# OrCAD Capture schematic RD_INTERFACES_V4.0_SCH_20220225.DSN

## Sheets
1 [1] REVISION HISTORY: title: REFERENCE DESIGN INTERFACE BOARD VERSION 3.2; rev: D
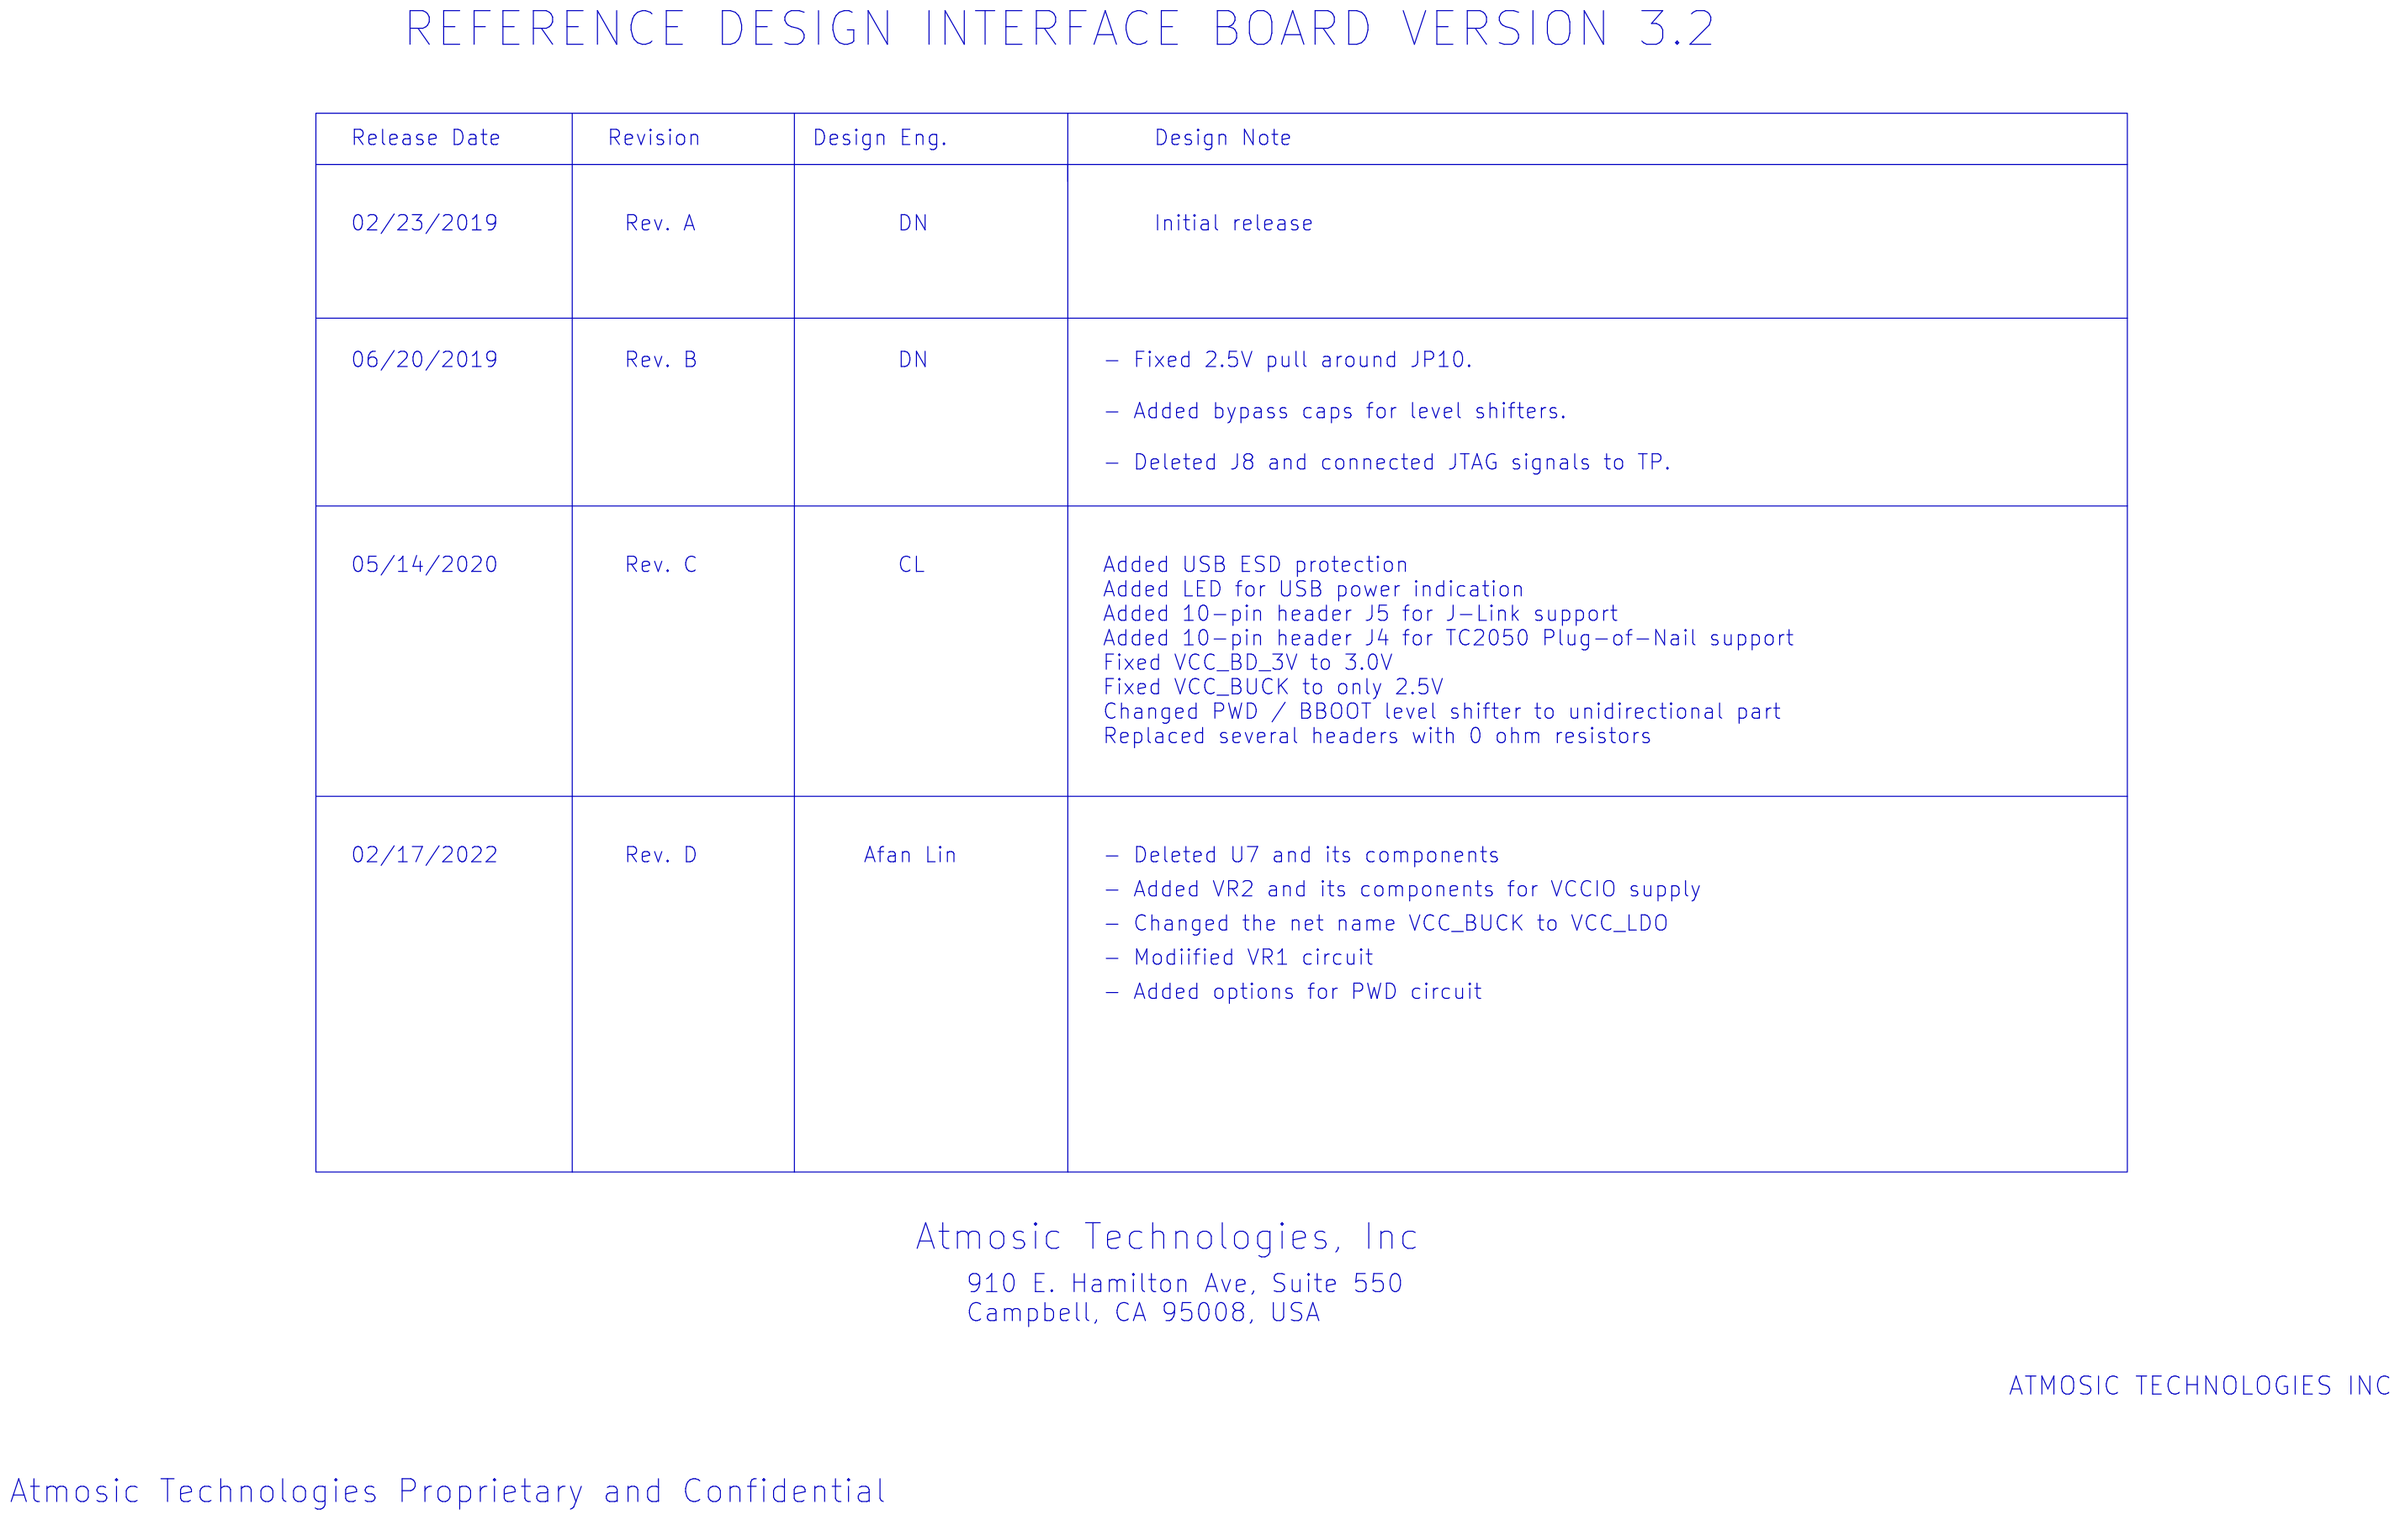
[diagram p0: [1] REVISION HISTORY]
2 [2] RD Connector: size B
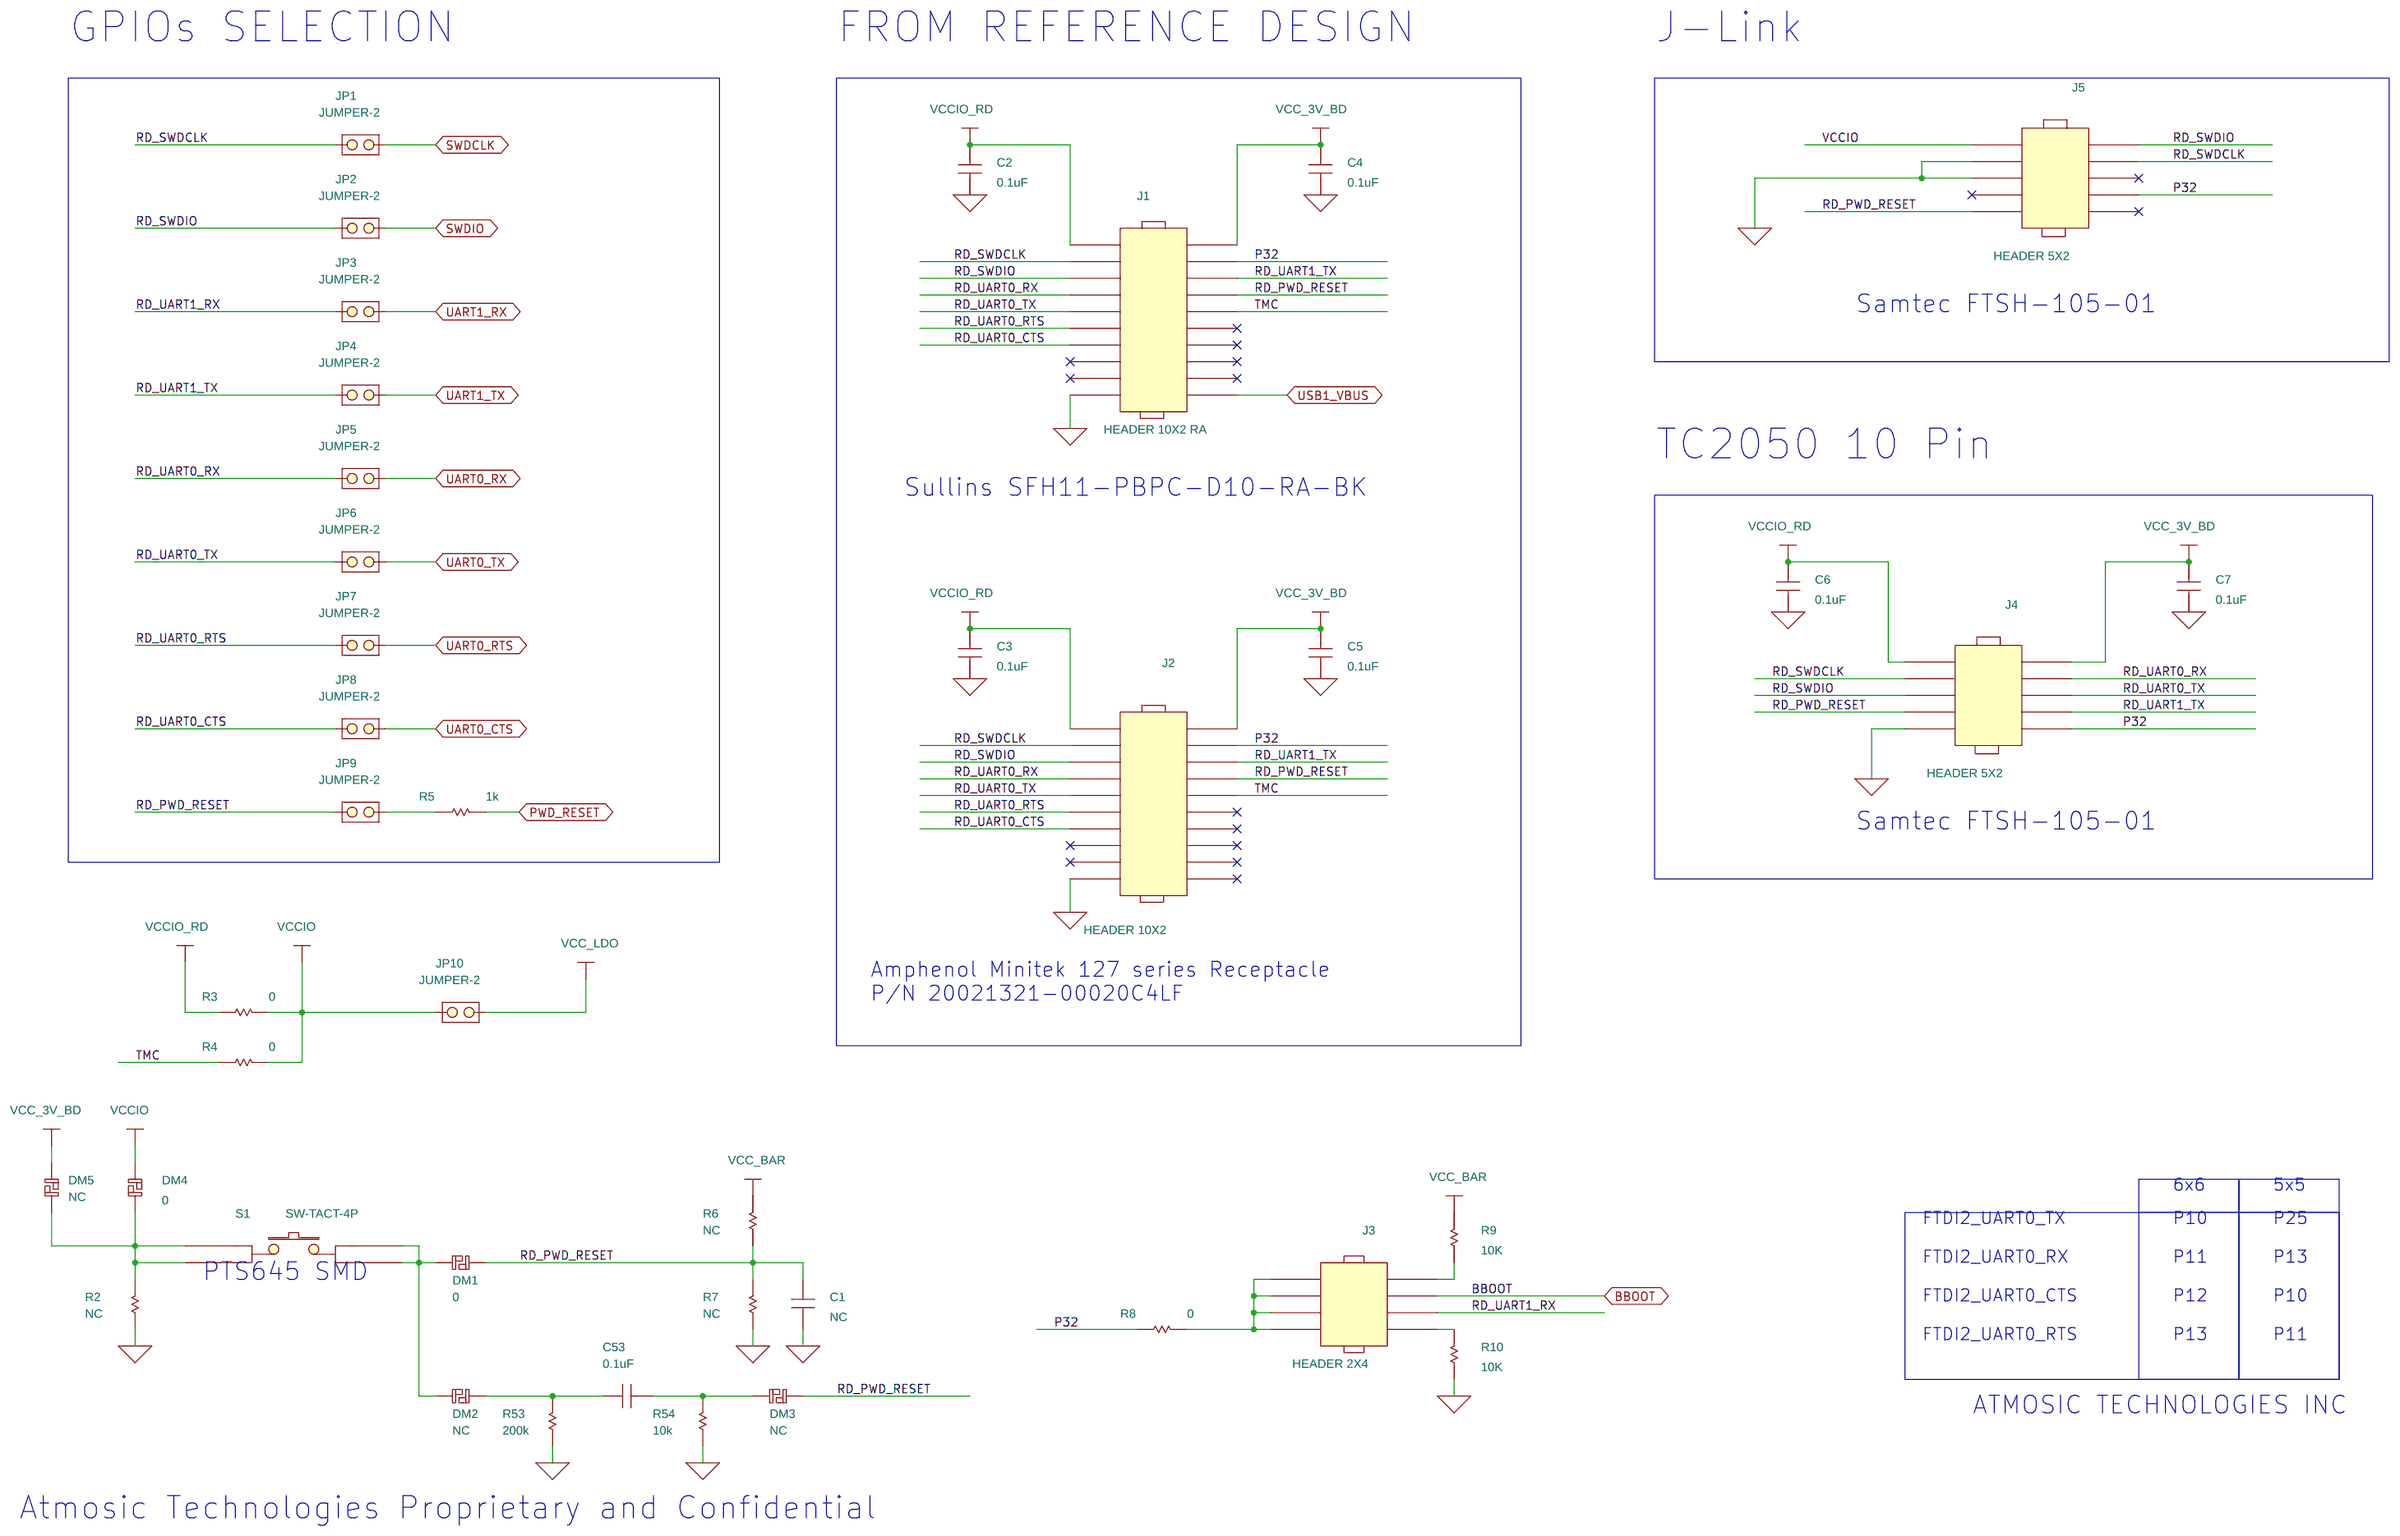
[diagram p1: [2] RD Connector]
3 [3] USB-Serial-MPSSE MODE: size B
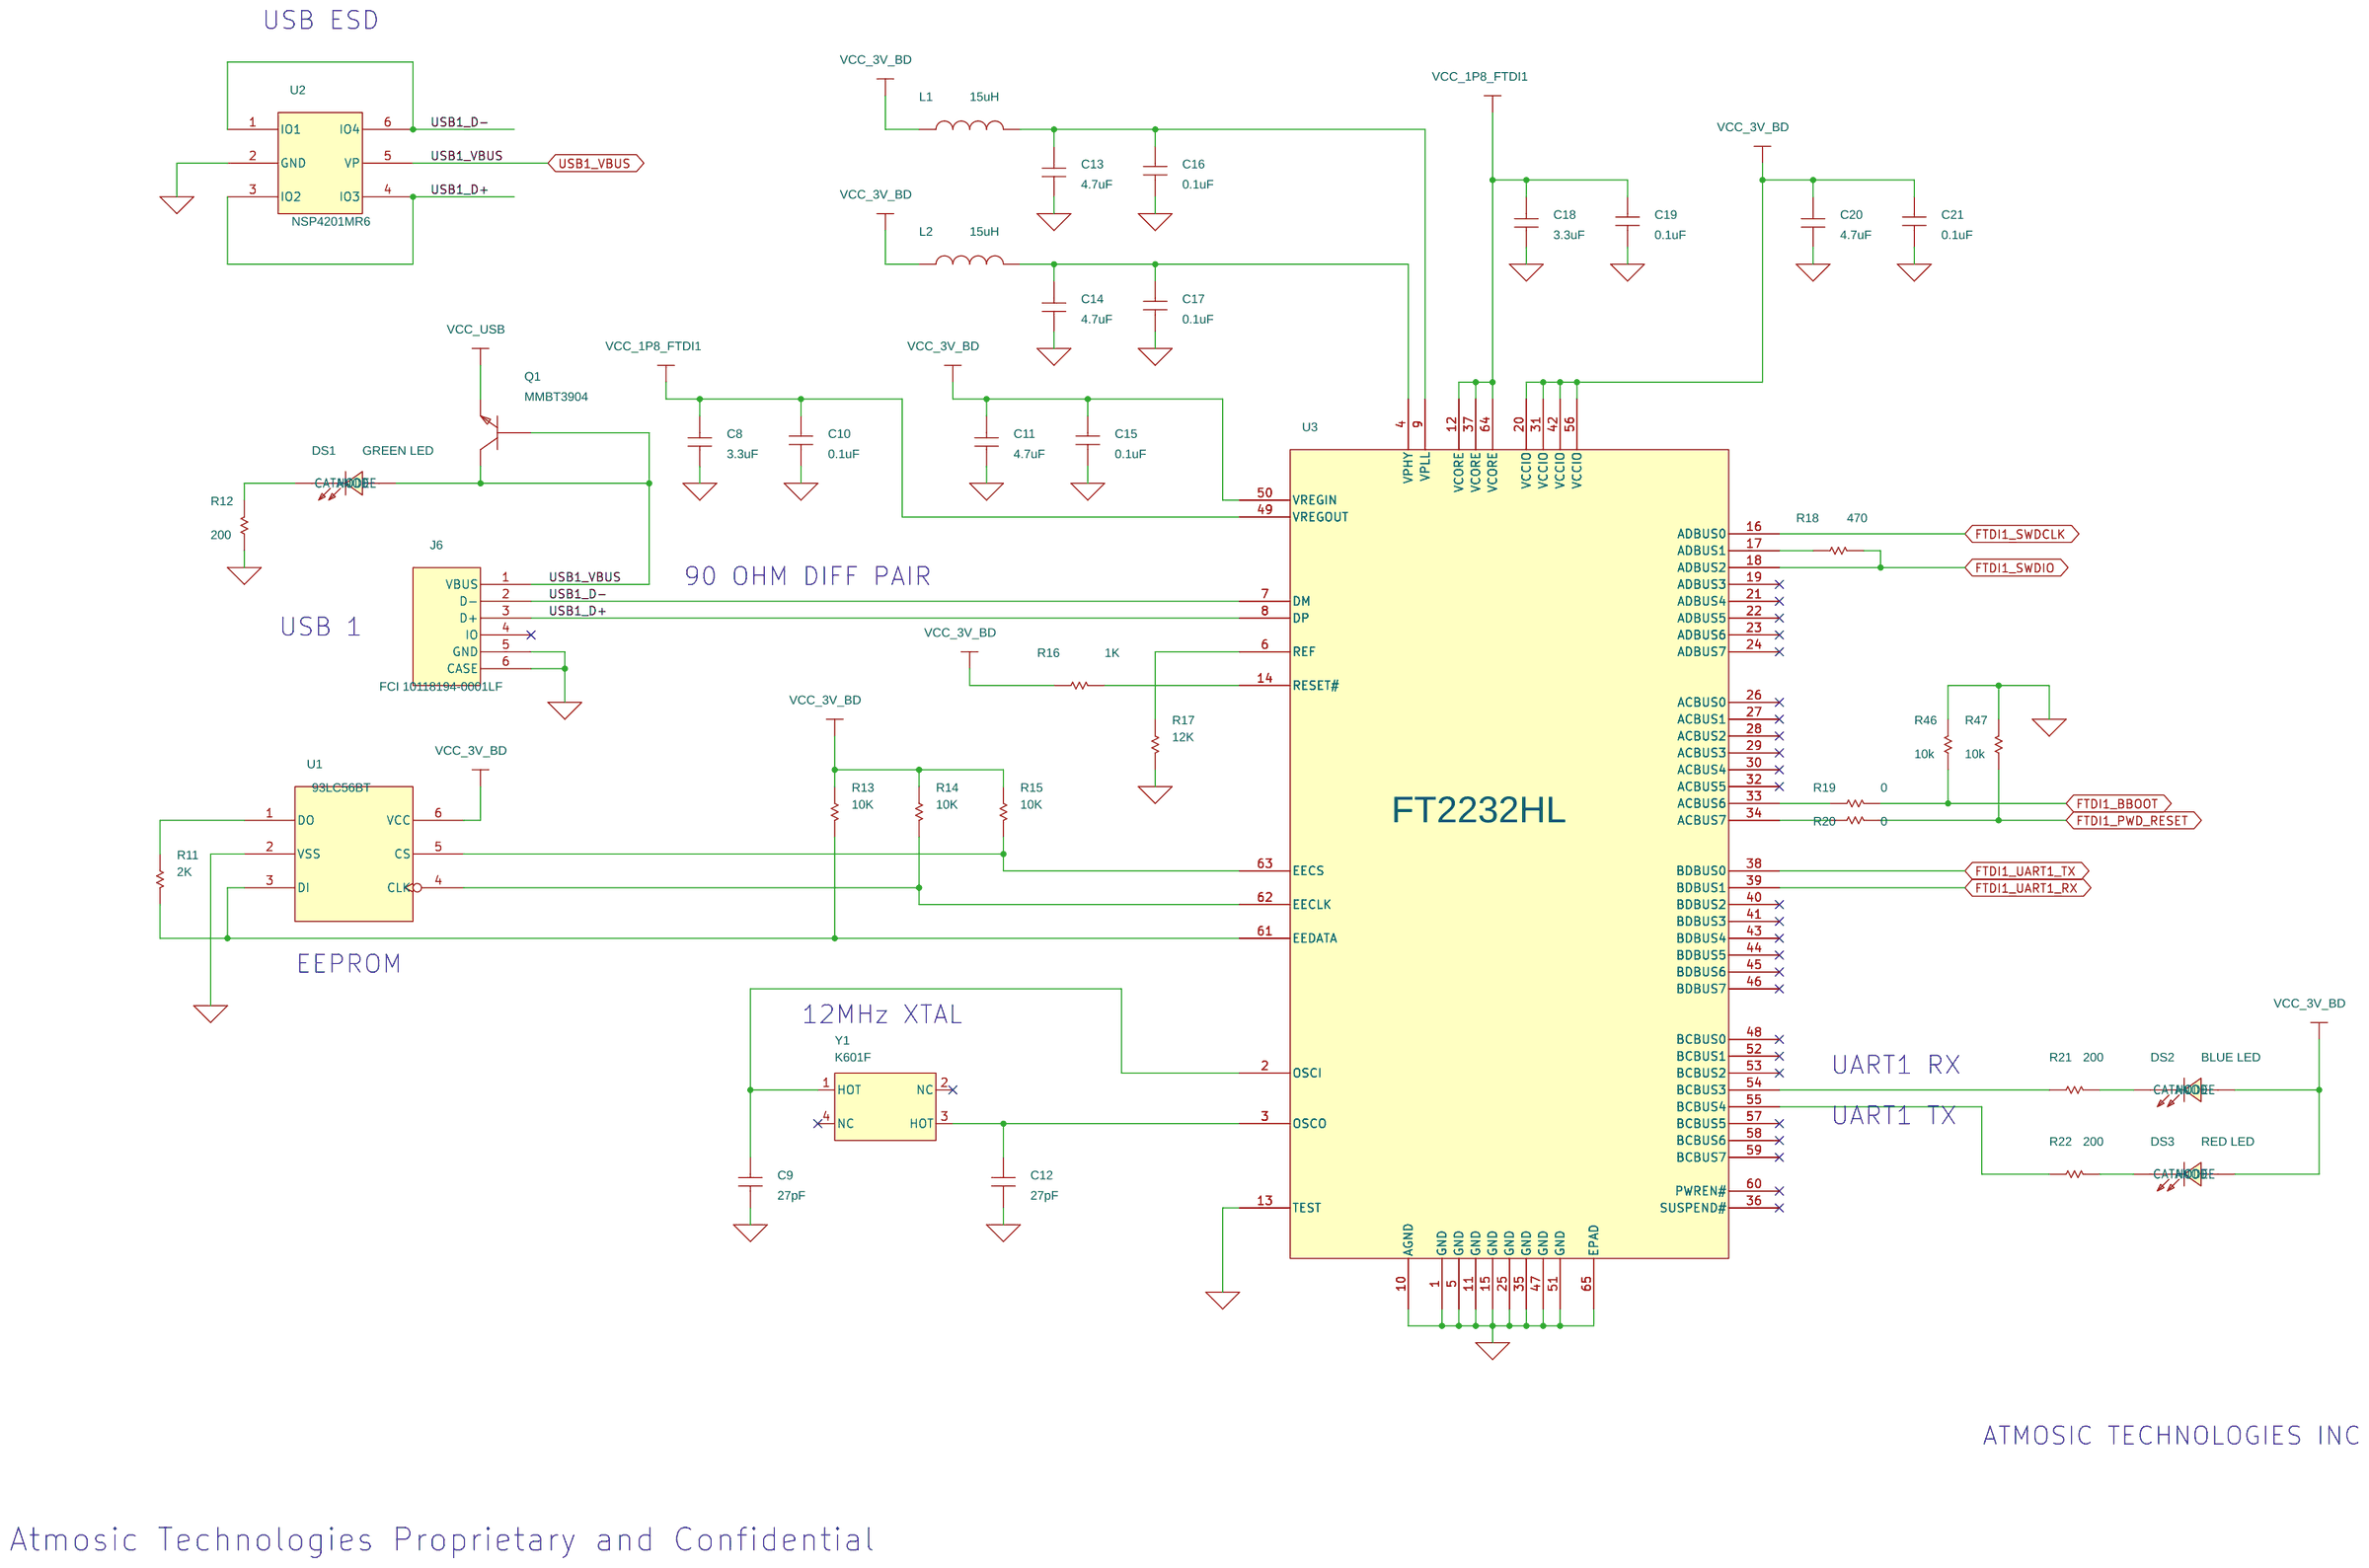
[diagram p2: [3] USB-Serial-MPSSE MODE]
4 [4] USB-Serial-UART MODE: size B
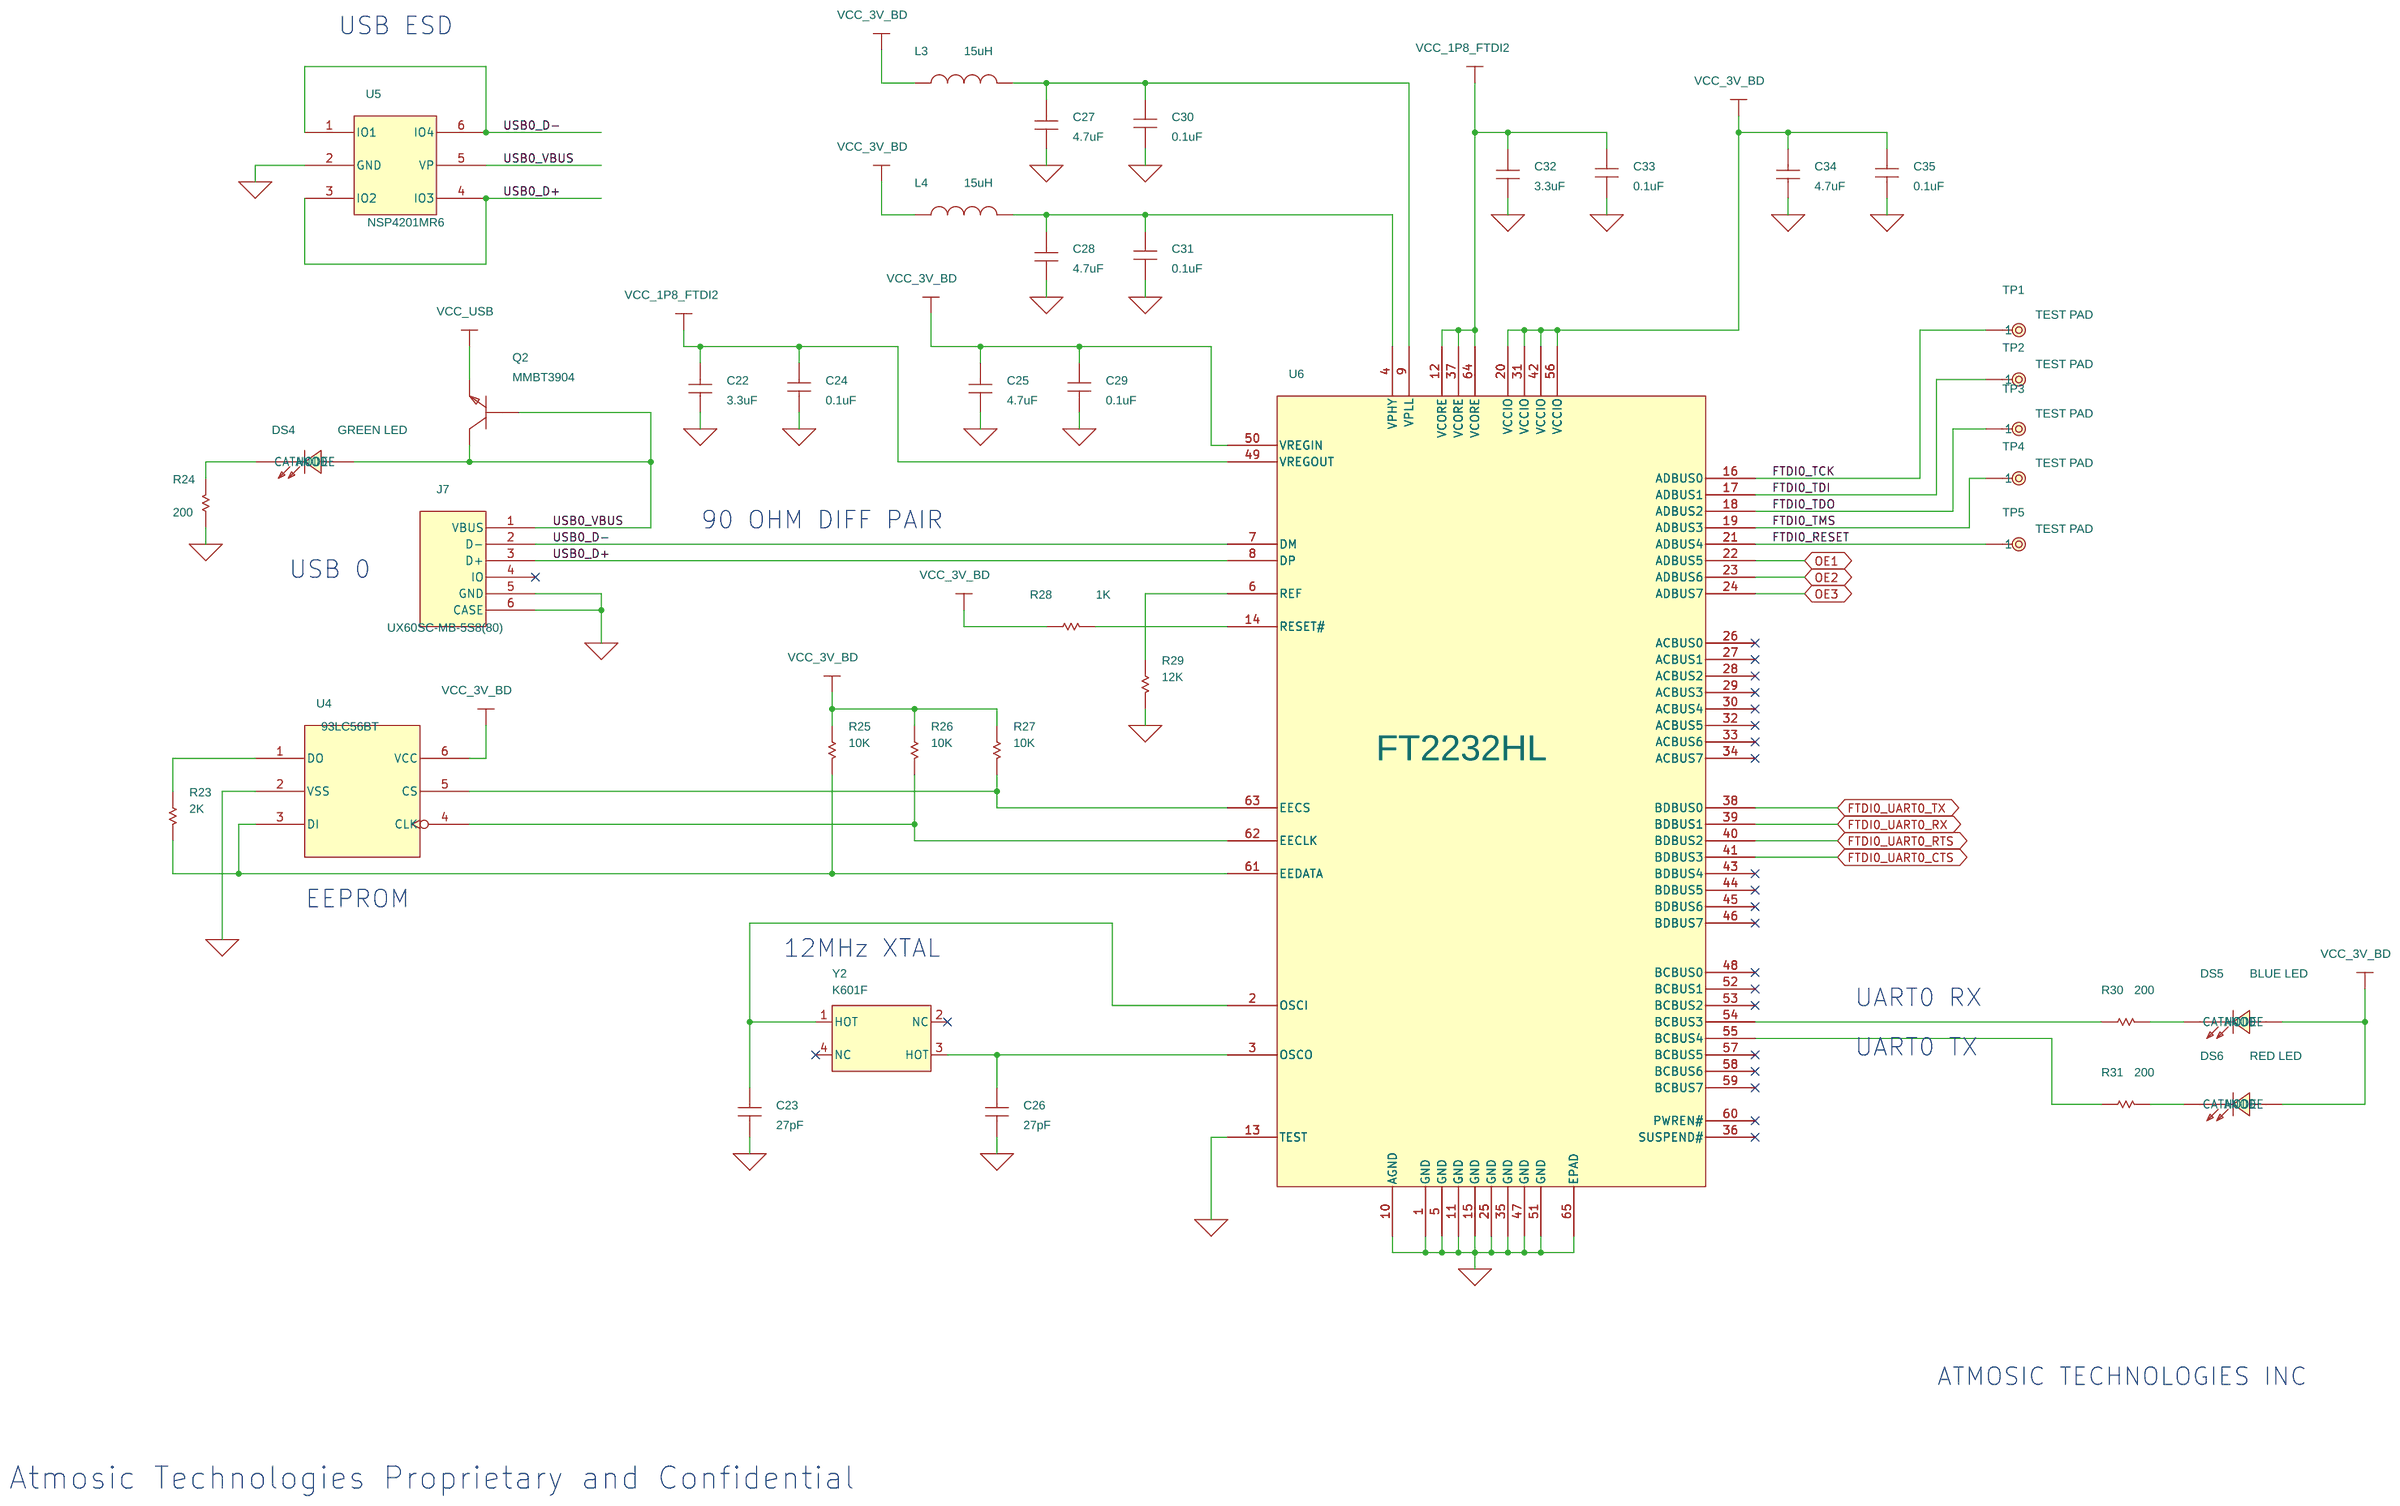
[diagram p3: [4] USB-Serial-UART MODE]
5 [5] Voltages Regulators: size B
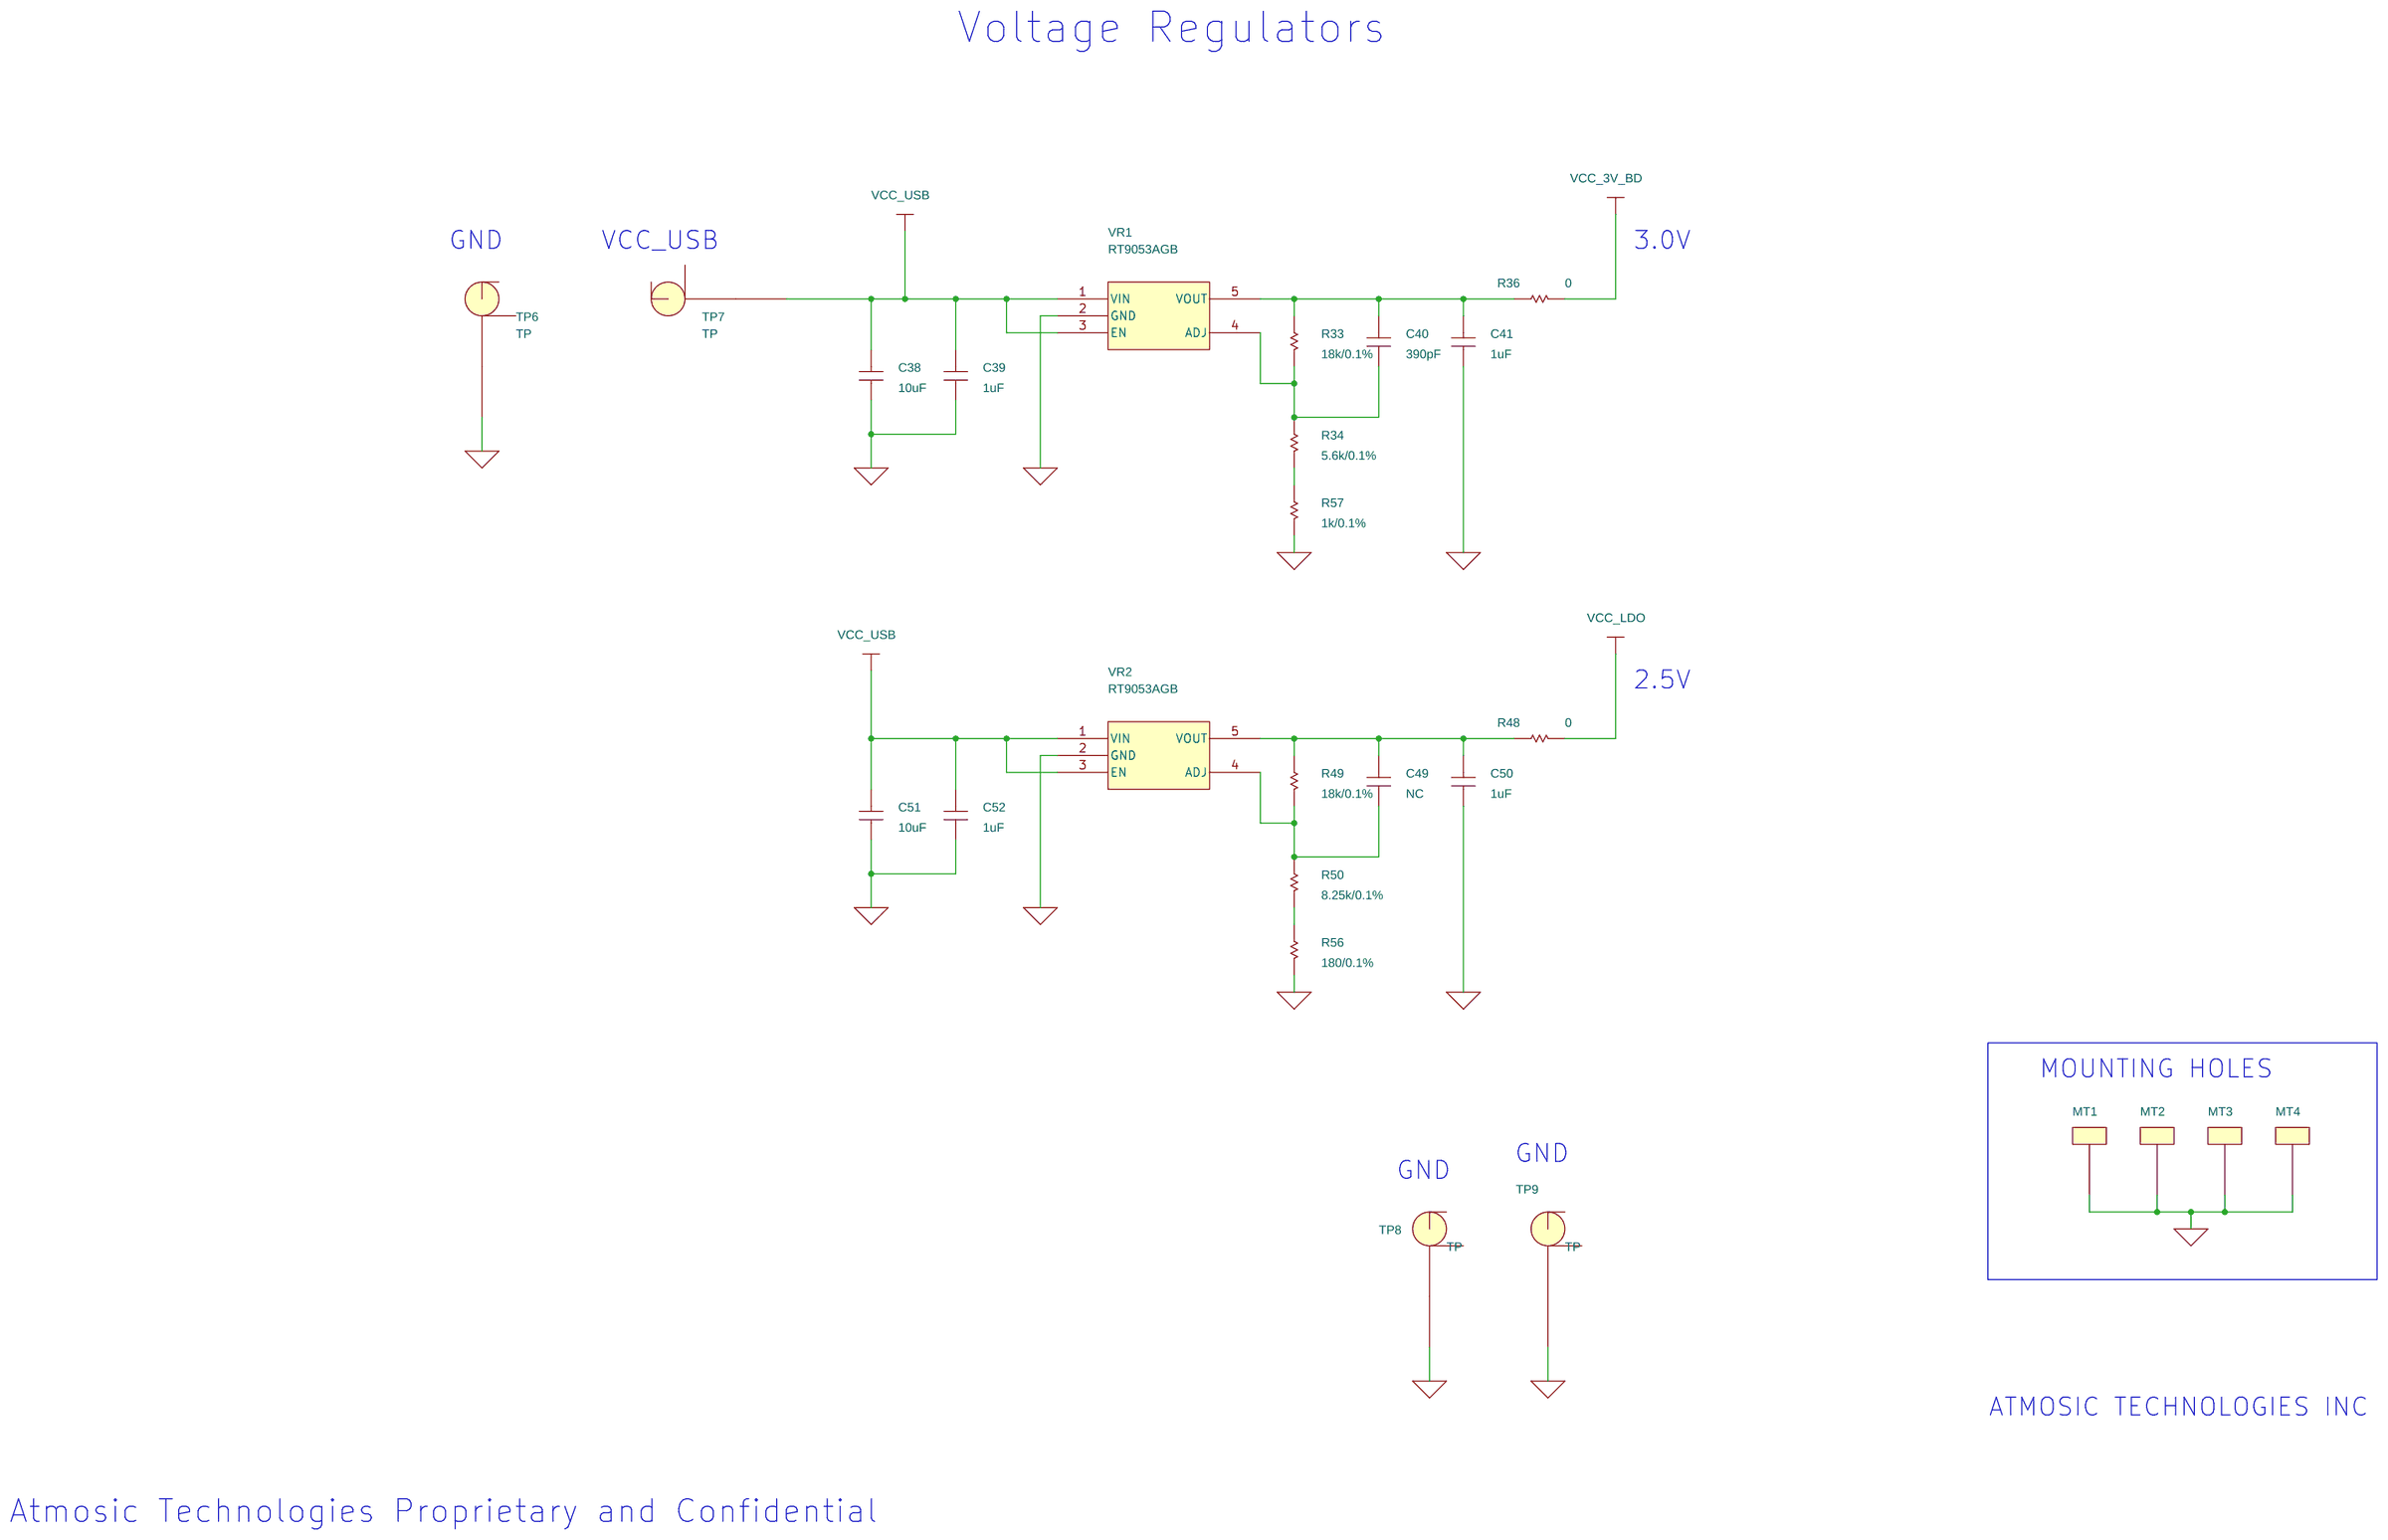
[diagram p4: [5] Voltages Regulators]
6 [6] Level Shifter: size B
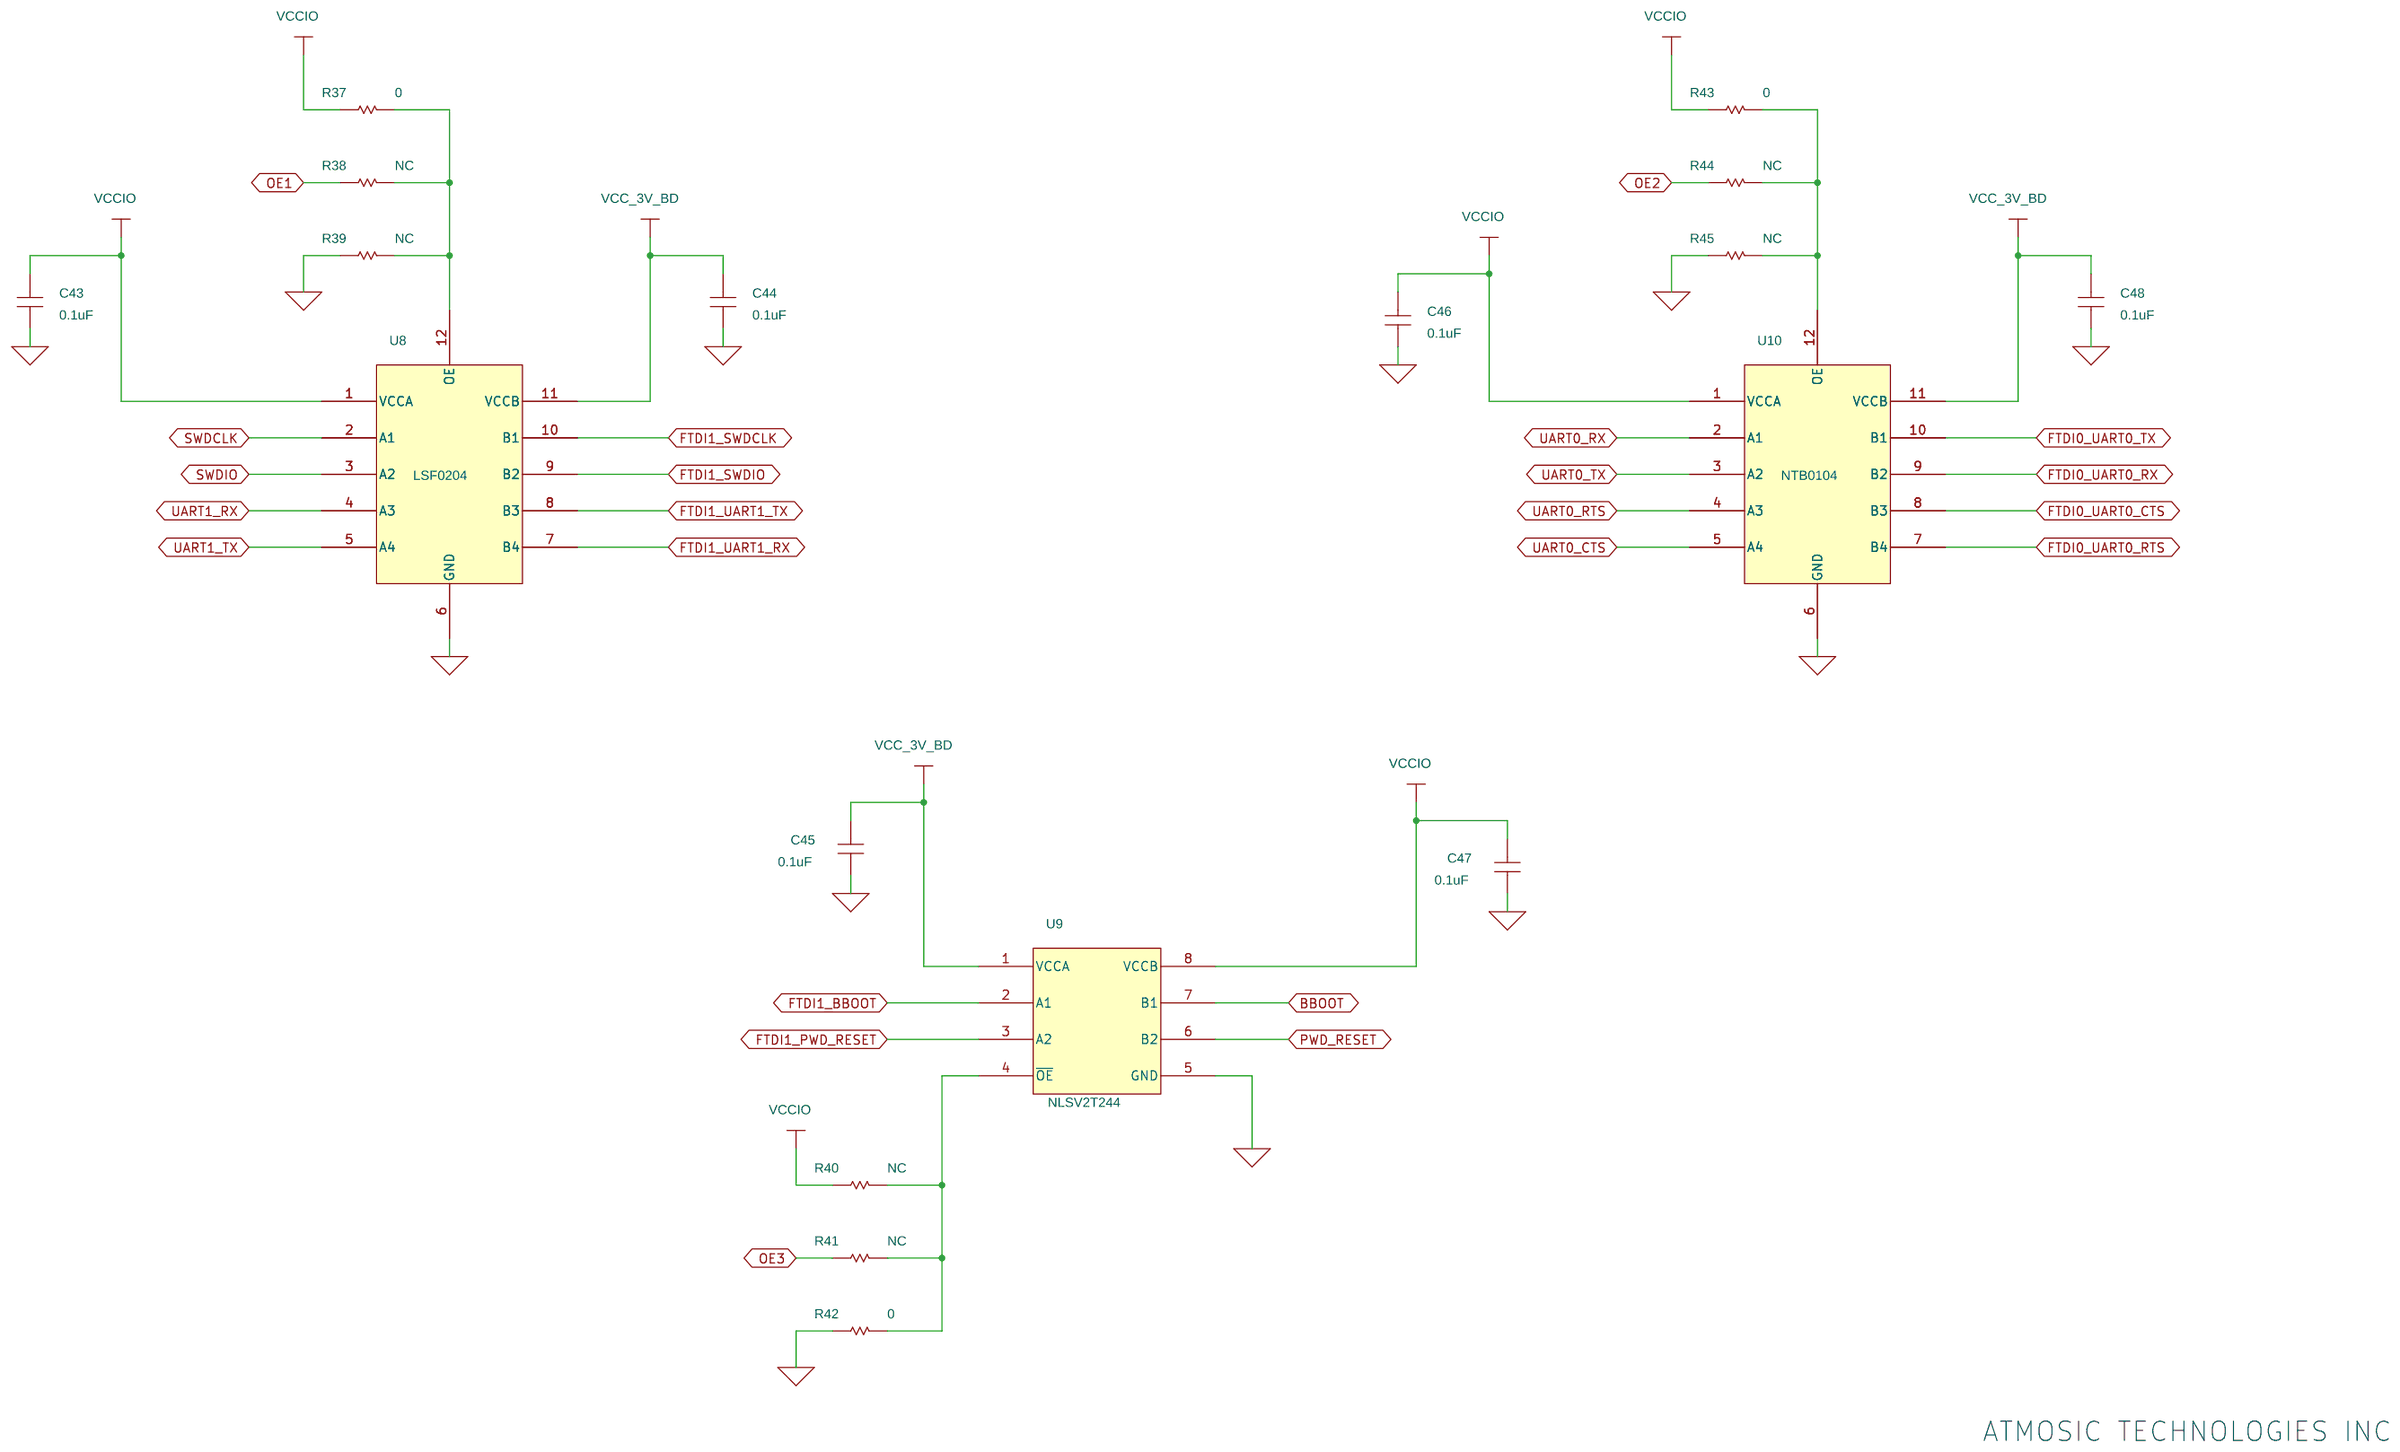
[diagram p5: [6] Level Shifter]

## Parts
sheet [2] RD Connector
C1  NC  [0603]
C2  0.1uF  [0402]
C3  0.1uF  [0402]
C4  0.1uF  [0402]
C5  0.1uF  [0402]
C6  0.1uF  [0402]
C7  0.1uF  [0402]
C53  0.1uF  [0402]
DM1  0  [0603-DUMMY]
DM2  NC  [0603-DUMMY]
DM3  NC  [0603-DUMMY]
DM4  0  [0603-DUMMY]
DM5  NC  [0603-DUMMY]
J1  HEADER 10X2 RA  [HDR10X2-RT-MATE]
J2  HEADER 10X2  [CON-FCI-2X10-1.27MM-SMD-NO-MT]
J3  HEADER 2X4  [HDR4X2]
J4  HEADER 5X2  [CON-SAMTEC-FTSH-10]
J5  HEADER 5X2  [CON-SAMTEC-FTSH-10]
JP1  JUMPER-2  [HDR1X2]
JP2  JUMPER-2  [HDR1X2]
JP3  JUMPER-2  [HDR1X2]
JP4  JUMPER-2  [HDR1X2]
JP5  JUMPER-2  [HDR1X2]
JP6  JUMPER-2  [HDR1X2]
JP7  JUMPER-2  [HDR1X2]
JP8  JUMPER-2  [HDR1X2]
JP9  JUMPER-2  [HDR1X2]
JP10  JUMPER-2  [HDR1X2]
R2  NC  [0603]
R3  0  [0603]
R4  0  [0603]
R5  1k  [0603]
R6  NC  [0603]
R7  NC  [0603]
R8  0  [0603]
R9  10K  [0603]
R10  10K  [0603]
R53  200k  [0402]
R54  10k  [0402]
S1  SW-TACT-4P  [SWI-SM-PTS645]
sheet [3] USB-Serial-MPSSE MODE
C8  3.3uF  [0603]
C9  27pF  [0402]
C10  0.1uF  [0402]
C11  4.7uF  [0603]
C12  27pF  [0402]
C13  4.7uF  [0603]
C14  4.7uF  [0603]
C15  0.1uF  [0402]
C16  0.1uF  [0402]
C17  0.1uF  [0402]
C18  3.3uF  [0603]
C19  0.1uF  [0402]
C20  4.7uF  [0603]
C21  0.1uF  [0402]
DS1  GREEN LED  [LED-0603]
DS2  BLUE LED  [LED-0603]
DS3  RED LED  [LED-0603]
J6  FCI 10118194-0001LF  [MICRO-USB-B-RECPT]
L1  15uH  [0402]
L2  15uH  [0402]
Q1  MMBT3904  [SOT23]
R11  2K  [0402]
R12  200  [0402]
R13  10K  [0402]
R14  10K  [0402]
R15  10K  [0402]
R16  1K  [0402]
R17  12K  [0402]
R18  470  [0402]
R19  0  [0603]
R20  0  [0603]
R21  200  [0402]
R22  200  [0402]
R46  10k  [0603]
R47  10k  [0603]
U1  93LC56BT  [SOT23-6]
U2  NSP4201MR6  [TSOP-6]
U3  FT2232HL  [QFN-64-9X9MM-0.5]
Y1  K601F  [CRY-SMD4-3.2X2.5MM]
sheet [4] USB-Serial-UART MODE
C22  3.3uF  [0603]
C23  27pF  [0402]
C24  0.1uF  [0402]
C25  4.7uF  [0603]
C26  27pF  [0402]
C27  4.7uF  [0603]
C28  4.7uF  [0603]
C29  0.1uF  [0402]
C30  0.1uF  [0402]
C31  0.1uF  [0402]
C32  3.3uF  [0603]
C33  0.1uF  [0402]
C34  4.7uF  [0603]
C35  0.1uF  [0402]
DS4  GREEN LED  [LED-0603]
DS5  BLUE LED  [LED-0603]
DS6  RED LED  [LED-0603]
J7  UX60SC-MB-5S8(80)  [HIROSE_UX60SCMB5S8]
L3  15uH  [0402]
L4  15uH  [0402]
Q2  MMBT3904  [SOT23]
R23  2K  [0402]
R24  200  [0402]
R25  10K  [0402]
R26  10K  [0402]
R27  10K  [0402]
R28  1K  [0402]
R29  12K  [0402]
R30  200  [0402]
R31  200  [0402]
TP1  TEST PAD  [TESTPAD50]
TP2  TEST PAD  [TESTPAD50]
TP3  TEST PAD  [TESTPAD50]
TP4  TEST PAD  [TESTPAD50]
TP5  TEST PAD  [TESTPAD50]
U4  93LC56BT  [SOT23-6]
U5  NSP4201MR6  [TSOP-6]
U6  FT2232HL  [QFN-64-9X9MM-0.5]
Y2  K601F  [CRY-SMD4-3.2X2.5MM]
sheet [5] Voltages Regulators
C38  10uF  [0603]
C39  1uF  [0603]
C40  390pF  [0603]
C41  1uF  [0603]
C49  NC  [0603]
C50  1uF  [0603]
C51  10uF  [0603]
C52  1uF  [0603]
MT1  TEST POINT  [HOLE-250R125]
MT2  TEST POINT  [HOLE-250R125]
MT3  TEST POINT  [HOLE-250R125]
MT4  TEST POINT  [HOLE-250R125]
R33  18k/0.1%  [0402]
R34  5.6k/0.1%  [0402]
R36  0  [0603]
R48  0  [0603]
R49  18k/0.1%  [0402]
R50  8.25k/0.1%  [0402]
R56  180/0.1%  [0402]
R57  1k/0.1%  [0402]
TP6  TP  [TESTPIN]
TP7  TP  [TESTPIN]
TP8  TP  [TESTPIN]
TP9  TP  [TESTPIN]
VR1  RT9053AGB  [SOT23-5]
VR2  RT9053AGB  [SOT23-5]
sheet [6] Level Shifter
C43  0.1uF  [0603]
C44  0.1uF  [0603]
C45  0.1uF  [0603]
C46  0.1uF  [0603]
C47  0.1uF  [0603]
C48  0.1uF  [0603]
R37  0  [0603]
R38  NC  [0603]
R39  NC  [0603]
R40  NC  [0603]
R41  NC  [0603]
R42  0  [0603]
R43  0  [0603]
R44  NC  [0603]
R45  NC  [0603]
U8  LSF0204  [QFN-12-1.7X2]
U9  NLSV2T244  [UDFN-8-1.8X1.2-0.4P]
U10  NTB0104  [QFN-12-1.7X2]

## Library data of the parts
C1-C35 C38-C41 C43-C53 = SMALL_CAP
DM1-DM5 = DUMMY
J1 J2 = HEADER_10X2
J3 = CON-4X2-F
J4 J5 = HEADER_5X2
JP1-JP10 = JUMPER-2
R2-R31 R33 R34 R36-R50 R53 R54 R56 R57 = SMALL_R1
S1 = SW-TACT-4P-5
DS1-DS6 = LED
J6 J7 = USB_CONN_0
L1-L4 = INDUCTOR
Q1 Q2 = MMBT3904_SOT
U1 U4 = 93LC56BT-I_OT
U2 U5 = NSP4201MR6_0
U3 U6 = FT2232HQ-REEL_2
Y1 Y2 = XTAL-OSC-4P_0
TP1-TP5 = TP_CLIP
MT1-MT4 = TEST_POINT
TP6-TP9 = TP_0
VR1 VR2 = VAR_REG
U8 U10 = NTB0104
U9 = NLSV2T244

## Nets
GND_SIGNAL: C1.2 C2.2 C3.2 C4.2 C5.2 C6.2 C7.2 C8.1 C9.2 C10.2 C11.1 C12.2 C13.1 C14.1 C15.2 C16.2 C17.2 C18.1 C19.2 C20.1 C21.2 C22.1 C23.2 C24.2 C25.1 C26.2 C27.1 C28.1 C29.2 C30.2 C31.2 C32.1 C33.2 C34.1 C35.2 C38.1 C39.1 C41.1 C43.1 C44.1 C45.1 C46.1 C47.1 C48.1 C50.1 C51.1 C52.1 J1.19 J2.19 J4.9 J5.3 J5.5 J6.5(GND) J6.6(CASE) J7.5(GND) J7.6(CASE) MT1.1 MT2.1 MT3.1 MT4.1 R2.1 R7.1 R10.1 R12.1 R17.2 R24.1 R29.2 R39.1 R42.1 R45.1 R46.2 R47.2 R53.1 R54.1 R56.2 R57.2 TP6.1(TP) TP8.1(TP) TP9.1(TP) U1.2(VSS) U2.2(GND) U3.1(GND) U3.5(GND) U3.10(AGND) U3.11(GND) U3.13(TEST) U3.15(GND) U3.25(GND) U3.35(GND) U3.47(GND) U3.51(GND) U3.65(EPAD) U4.2(VSS) U5.2(GND) U6.1(GND) U6.5(GND) U6.10(AGND) U6.11(GND) U6.13(TEST) U6.15(GND) U6.25(GND) U6.35(GND) U6.47(GND) U6.51(GND) U6.65(EPAD) U8.6(GND) U9.5(GND) U10.6(GND) VR1.2(GND) VR2.2(GND)
VCC_1P8_FTDI1: C8.2 C10.1 C18.2 C19.1 U3.12(VCORE) U3.37(VCORE) U3.49(VREGOUT) U3.64(VCORE)
VCC_1P8_FTDI2: C22.2 C24.1 C32.2 C33.1 U6.12(VCORE) U6.37(VCORE) U6.49(VREGOUT) U6.64(VCORE)
VCC_3V_BD: C4.1 C5.1 C7.1 C11.2 C15.1 C20.2 C21.1 C25.2 C29.1 C34.2 C35.1 C44.2 C45.2 C48.2 DM5.1 DS2.2(ANODE) DS3.2(ANODE) DS5.2(ANODE) DS6.2(ANODE) J1.2 J2.2 J4.2 L1.1 L2.1 L3.1 L4.1 R13.1 R14.1 R15.1 R16.1 R25.1 R26.1 R27.1 R28.1 R36.2 U1.6(VCC) U3.20(VCCIO) U3.31(VCCIO) U3.42(VCCIO) U3.50(VREGIN) U3.56(VCCIO) U4.6(VCC) U6.20(VCCIO) U6.31(VCCIO) U6.42(VCCIO) U6.50(VREGIN) U6.56(VCCIO) U8.11(VCCB) U9.1(VCCA) U10.11(VCCB)
VCC_LDO: JP10.2 R48.2
VCC_USB: C38.2 C39.2 C51.2 C52.2 Q1.2(E) Q2.2(E) TP7.1(TP) VR1.1(VIN) VR1.3(EN) VR2.1(VIN) VR2.3(EN)
VCCIO: C43.2 C46.2 C47.2 DM4.1 J5.1 JP10.1 R3.2 R4.2 R6.2 R9.2 R37.1 R40.1 R43.1 U8.1(VCCA) U9.8(VCCB) U10.1(VCCA)
VCCIO_RD: C2.1 C3.1 C6.1 J1.1 J2.1 J4.1 R3.1
BBOOT: J3.4 U9.7(B1)
FTDI0_RESET: TP5.1 U6.21(ADBUS4)
FTDI0_TCK: TP1.1 U6.16(ADBUS0)
FTDI0_TDI: TP2.1 U6.17(ADBUS1)
FTDI0_TDO: TP3.1 U6.18(ADBUS2)
FTDI0_TMS: TP4.1 U6.19(ADBUS3)
FTDI0_UART0_CTS: U6.41(BDBUS3) U10.8(B3)
FTDI0_UART0_RTS: U6.40(BDBUS2) U10.7(B4)
FTDI0_UART0_RX: U6.39(BDBUS1) U10.9(B2)
FTDI0_UART0_TX: U6.38(BDBUS0) U10.10(B1)
FTDI1_BBOOT: R19.2 R46.1 U9.2(A1)
FTDI1_PWD_RESET: R20.2 R47.1 U9.3(A2)
FTDI1_SWDCLK: U3.16(ADBUS0) U8.10(B1)
FTDI1_SWDIO: R18.2 U3.18(ADBUS2) U8.9(B2)
FTDI1_UART1_RX: U3.39(BDBUS1) U8.7(B4)
FTDI1_UART1_TX: U3.38(BDBUS0) U8.8(B3)
OE1: R38.1 U6.22(ADBUS5)
OE2: R44.1 U6.23(ADBUS6)
OE3: R41.1 U6.24(ADBUS7)
P32: J1.4 J2.4 J4.10 J5.8 R8.1
PWD_RESET: R5.2 U9.6(B2)
RD_PWD_RESET: C1.1 DM1.2 DM3.2 J1.8 J2.8 J4.7 J5.9 JP9.1 R6.1 R7.2
RD_SWDCLK: J1.3 J2.3 J4.3 J5.4 JP1.1
RD_SWDIO: J1.5 J2.5 J4.5 J5.2 JP2.1
RD_UART0_CTS: J1.13 J2.13 JP8.1
RD_UART0_RTS: J1.11 J2.11 JP7.1
RD_UART0_RX: J1.7 J2.7 J4.4 JP5.1
RD_UART0_TX: J1.9 J2.9 J4.6 JP6.1
RD_UART1_RX: J3.6 JP3.1
RD_UART1_TX: J1.6 J2.6 J4.8 JP4.1
SWDCLK: JP1.2 U8.2(A1)
SWDIO: JP2.2 U8.3(A2)
TMC: J1.10 J2.10 R4.1
UART0_CTS: JP8.2 U10.5(A4)
UART0_RTS: JP7.2 U10.4(A3)
UART0_RX: JP5.2 U10.2(A1)
UART0_TX: JP6.2 U10.3(A2)
UART1_RX: JP3.2 U8.4(A3)
UART1_TX: JP4.2 U8.5(A4)
USB0_D+: J7.3(D+) U5.3(IO2) U5.4(IO3) U6.8(DP)
USB0_D-: J7.2(D-) U5.1(IO1) U5.6(IO4) U6.7(DM)
USB0_VBUS: DS4.2(ANODE) J7.1(VBUS) Q2.1(B) Q2.3(C) U5.5(VP)
USB1_D+: J6.3(D+) U2.3(IO2) U2.4(IO3) U3.8(DP)
USB1_D-: J6.2(D-) U2.1(IO1) U2.6(IO4) U3.7(DM)
USB1_VBUS: DS1.2(ANODE) J1.20 J6.1(VBUS) Q1.1(B) Q1.3(C) U2.5(VP)
N16292774: C14.2 C17.1 L2.2 U3.4(VPHY)
N16292979: C13.2 C16.1 L1.2 U3.9(VPLL)
N16294050: C12.1 U3.3(OSCO) Y1.3(HOT)
N16294054: C9.1 U3.2(OSCI) Y1.1(HOT)
N16296332: R17.1 U3.6(REF)
N16296638: R15.2 U1.5(CS) U3.63(EECS)
N16296642: R14.2 U1.4(CLK) U3.62(EECLK)
N16296646: R11.2 R13.2 U1.3(DI) U3.61(EEDATA)
N16326628: R16.2 U3.14(RESET#)
N16330106: R18.1 U3.17(ADBUS1)
N16346064: R11.1 U1.1(DO)
N16351056: R27.2 U4.5(CS) U6.63(EECS)
N16351060: R26.2 U4.4(CLK) U6.62(EECLK)
N16351064: R23.2 R25.2 U4.3(DI) U6.61(EEDATA)
N16351344: R28.2 U6.14(RESET#)
N16351434: C28.2 C31.1 L4.2 U6.4(VPHY)
N16351514: C27.2 C30.1 L3.2 U6.9(VPLL)
N16351914: C26.1 U6.3(OSCO) Y2.3(HOT)
N16351918: C23.1 U6.2(OSCI) Y2.1(HOT)
N16351974: R23.1 U4.1(DO)
N16352290: R29.1 U6.6(REF)
N16370384: C40.2 C41.2 R33.1 R36.1 VR1.5(VOUT)
N16370510: C40.1 R33.2 R34.1 VR1.4(ADJ)
N16466896: R20.1 U3.34(ACBUS7)
N16489007: DS6.1(CATHODE) R31.2
N16489011: DS5.1(CATHODE) R30.2
N16489051: R31.1 U6.55(BCBUS4)
N16489152: R30.1 U6.54(BCBUS3)
N16526562: R19.1 U3.33(ACBUS6)
N16610682: DS3.1(CATHODE) R22.2
N16610686: DS2.1(CATHODE) R21.2
N16610722: R21.1 U3.54(BCBUS3)
N16610726: R22.1 U3.55(BCBUS4)
N16779969: J3.2 R9.1
N16779985: J3.1 J3.3 J3.5 J3.7 R8.2
N16780025: J3.8 R10.2
N16807888: R37.2 R38.2 R39.2 U8.12(OE)
N16808373: R43.2 R44.2 R45.2 U10.12(OE)
N16808703: R40.2 R41.2 R42.2 U9.4(~{OE})
N16813141: JP9.2 R5.1
N16843444: DS4.1(CATHODE) R24.2
N16843906: DS1.1(CATHODE) R12.2
N16850039: DM4.2 DM5.2 R2.2 S1.1 S1.2
N16850063: DM1.1 DM2.1 S1.3 S1.4
N16881565: C49.2 C50.2 R48.1 R49.1 VR2.5(VOUT)
N16881587: C49.1 R49.2 R50.1 VR2.4(ADJ)
N16882996: C53.1 DM2.2 R53.2
N16883004: C53.2 DM3.1 R54.2
N16884017: R50.2 R56.1
N16884989: R34.2 R57.1

Not connected (* = marked no-connect by the designer): J1 12* 14* 15* 16* 17* 18*; J2 12* 14* 15* 16* 17* 18* 20*; J5 6* 7* 10*; J6 4(IO)*; J7 4(IO)*; U3 19(ADBUS3)* 21(ADBUS4)* 22(ADBUS5)* 23(ADBUS6)* 24(ADBUS7)* 26(ACBUS0)* 27(ACBUS1)* 28(ACBUS2)* 29(ACBUS3)* 30(ACBUS4)* 32(ACBUS5)* 36(SUSPEND#)* 40(BDBUS2)* 41(BDBUS3)* 43(BDBUS4)* 44(BDBUS5)* 45(BDBUS6)* 46(BDBUS7)* 48(BCBUS0)* 52(BCBUS1)* 53(BCBUS2)* 57(BCBUS5)* 58(BCBUS6)* 59(BCBUS7)* 60(PWREN#)*; U6 26(ACBUS0)* 27(ACBUS1)* 28(ACBUS2)* 29(ACBUS3)* 30(ACBUS4)* 32(ACBUS5)* 33(ACBUS6)* 34(ACBUS7)* 36(SUSPEND#)* 43(BDBUS4)* 44(BDBUS5)* 45(BDBUS6)* 46(BDBUS7)* 48(BCBUS0)* 52(BCBUS1)* 53(BCBUS2)* 57(BCBUS5)* 58(BCBUS6)* 59(BCBUS7)* 60(PWREN#)*; Y1 2(NC)* 4(NC)*; Y2 2(NC)* 4(NC)*

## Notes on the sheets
sheet 1
- REFERENCE DESIGN INTERFACE BOARD VERSION 3.2
- Release Date
- Revision
- Design Eng.
- Design Note
- 02/23/2019
- Rev. A
- DN
- Initial release
- 06/20/2019
- Rev. B
- DN
- - Fixed 2.5V pull around JP10.
- - Added bypass caps for level shifters.
- - Deleted J8 and connected JTAG signals to TP.
- 05/14/2020
- Rev. C
- CL
- Added USB ESD protection
  Added LED for USB power indication
  Added 10-pin header J5 for J-Link support
  Added 10-pin header J4 for TC2050 Plug-of-Nail support
  Fixed VCC_BD_3V to 3.0V
  Fixed VCC_BUCK to only 2.5V
  Changed PWD / BBOOT level shifter to unidirectional part
  Replaced several headers with 0 ohm resistors
- 02/17/2022
- Rev. D
- Afan Lin
- - Deleted U7 and its components
- - Added VR2 and its components for VCCIO supply
- - Changed the net name VCC_BUCK to VCC_LDO
- - Modiified VR1 circuit
- - Added options for PWD circuit
- Atmosic Technologies, Inc
- 910 E. Hamilton Ave, Suite 550
  Campbell, CA 95008, USA
- ATMOSIC TECHNOLOGIES INC
- Atmosic Technologies Proprietary and Confidential
sheet 2
- GPIOs SELECTION
- FROM REFERENCE DESIGN
- J-Link
- Samtec FTSH-105-01
- TC2050 10 Pin
- Sullins SFH11-PBPC-D10-RA-BK
- Samtec FTSH-105-01
- Amphenol Minitek 127 series Receptacle
  P/N 20021321-00020C4LF
- 6x6
- 5x5
- FTDI2_UART0_TX
  FTDI2_UART0_RX
  FTDI2_UART0_CTS
  FTDI2_UART0_RTS
- P10
  P11
  P12
  P13
- P25
  P13
  P10
  P11
- PTS645 SMD
- ATMOSIC TECHNOLOGIES INC
- Atmosic Technologies Proprietary and Confidential
sheet 3
- USB ESD
- 90 OHM DIFF PAIR
- USB 1
- EEPROM
- 12MHz XTAL
- UART1 RX
- UART1 TX
- ATMOSIC TECHNOLOGIES INC
- Atmosic Technologies Proprietary and Confidential
sheet 4
- USB ESD
- 90 OHM DIFF PAIR
- USB 0
- EEPROM
- 12MHz XTAL
- UART0 RX
- UART0 TX
- ATMOSIC TECHNOLOGIES INC
- Atmosic Technologies Proprietary and Confidential
sheet 5
- Voltage Regulators
- GND
- VCC_USB
- 3.0V
- 2.5V
- MOUNTING HOLES
- GND
- GND
- ATMOSIC TECHNOLOGIES INC
- Atmosic Technologies Proprietary and Confidential
sheet 6
- ATMOSIC TECHNOLOGIES INC
